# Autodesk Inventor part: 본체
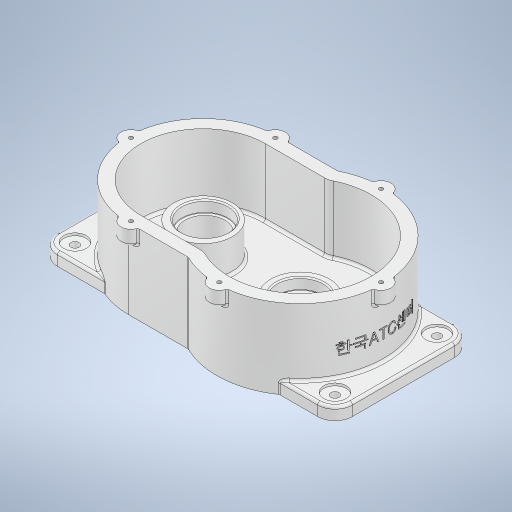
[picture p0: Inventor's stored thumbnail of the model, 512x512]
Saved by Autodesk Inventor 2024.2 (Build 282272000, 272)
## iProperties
Created: 2025-09
Part Number: 본체
Material: 알루미늄 6061
Document SubType Name: Modeling
Designer: home
Density: 2.7 g/cm^3
Appearance: 알루미늄 - 평지
Mass: 1651.06 g
Surface Area: 1337.51 cm^2
Volume: 611.503 cm^3
Author: home
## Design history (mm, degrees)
sketch "스케치1"
  geometry: L1 (118.5, -55)-(-118.5, -55); L2 (-118.5, -55)-(-118.5, 55); L3 (-118.5, 55)-(118.5, 55); L4 (118.5, 55)-(118.5, -55); 3 further points
  constraints: 8 end point, 2 midpoint, 2 parallel, 1 horizontal, 1 horizontal alignment, 1 perpendicular, 1 vertical alignment
  dimensions: "d0" = 110 distance of L3.end L1.start; "d1" = 237 distance of L1.start L1.end
extrude "돌출1" new body sketch "스케치1" distance "d2" = 10; taper "d3" = 0 deg
sketch "스케치2"
  geometry: L1 (-118.5, -55)-(118.5, -55) reference; L2 (-118.5, 55)-(-118.5, -55) reference; L3 (118.5, 55)-(-118.5, 55) reference; L4 (118.5, -55)-(118.5, 55) reference; L5 (42.5, -50)-(-4.988, -50); L6 (42.5, 50)-(-4.988, 50); L7 (-4.988, -60)-(42.5, -60); L8 (42.5, 60)-(-4.988, 60); A1 r 57 centre (-35.5, 0) between (-10.654, 51.3) and (-10.654, -51.3); A2 r 50 centre (42.5, 0) between (42.5, -50) and (42.5, 50); A3 r 13 centre (-4.988, -63) between (-4.988, -50) and (-10.654, -51.3); A4 r 13 centre (-4.988, 63) between (-10.654, 51.3) and (-4.988, 50); A5 r 3 centre (-4.988, -63) between (-4.988, -60) and (-6.295, -60.3); A6 r 60 centre (42.5, 0) between (42.5, -60) and (42.5, 60); A7 r 3 centre (-4.988, 63) between (-6.295, 60.3) and (-4.988, 60); A8 r 67 centre (-35.5, 0) between (-6.295, 60.3) and (-6.295, -60.3); 3 further points
  constraints: 18 point on circle, 8 centre point, 8 end point, 6 tangent, 2 horizontal, 2 horizontal alignment, 2 point on line, 1 equal radius, 5 other
  dimensions: "d4" = 114 diameter of A1; "d5" = 100 diameter of A2; "d6" = 78 distance of A1.centre A2.centre; "d11" = 76 distance from line of L4 A2.centre; "d12" = 13 radius of A3; "d13" = 10 radial gap between concentric circles of A1 A8
extrude "돌출3" join sketch "스케치2" distance "d14" = 64; taper "d15" = 0 deg
sketch "스케치3"
  geometry: 1 further point
sketch "스케치4"
  geometry: L1 (-66.479, 55)-(-118.5, 55) reference; L2 (-118.5, 55)-(-118.5, -55) reference; L3 (-118.5, -55)-(-66.479, -55) reference; A1 r 60 centre (-42.5, 0) between (-66.479, 55) and (-66.479, -55) reference; 1 further point
fillet "모깎기1" dims "d16" = 14
sketch "스케치5"
  geometry: L1 (20.533, -55)-(50.467, -55) reference; L2 (50.467, 55)-(20.533, 55) reference; A1 r 57 centre (35.5, 0) between (10.654, -51.3) and (10.654, 51.3) reference; 1 further point
extrude "돌출4" join sketch "스케치5" distance "d17" = 10; taper "d18" = 0 deg
sketch "스케치6"
  geometry: C1 r 9 at (-104.5, 41); C2 r 9 at (-104.5, -41); C3 r 9 at (104.5, 41); C4 r 9 at (104.5, -41); A1 r 14 centre (-104.5, 41) between (-104.5, 55) and (-118.5, 41) reference; A2 r 14 centre (-104.5, -41) between (-118.5, -41) and (-104.5, -55) reference; A3 r 14 centre (104.5, 41) between (118.5, 41) and (104.5, 55) reference; A4 r 14 centre (104.5, -41) between (104.5, -55) and (118.5, -41) reference; 1 further point
  constraints: 4 centre point, 4 coincident
  dimensions: "d19" = 18 diameter of C1; "d20" = 18 diameter of C3; "d21" = 18 diameter of C4; "d22" = 18 diameter of C2
extrude "돌출5" cut sketch "스케치6" distance "d23" = 2; taper "d24" = 0 deg
sketch "스케치7"
  geometry: C1 r 9 at (0, 0) reference; C2 r 9 at (209, 0) reference; C3 r 9 at (209, -82) reference; C4 r 9 at (0, -82) reference; C5 r 3.3 at (0, 0); C6 r 3.3 at (209, 0); C7 r 3.3 at (209, -82); C8 r 3.3 at (0, -82); 1 further point
  constraints: 4 centre point, 4 coincident
  dimensions: "d25" = 6.6 diameter of C5; "d26" = 6.6 diameter of C6; "d27" = 6.6 diameter of C7; "d28" = 6.6 diameter of C8
extrude "돌출6" cut sketch "스케치7" extent not by distance; stored distance "d29" = 2; taper "d30" = 0 deg
sketch "스케치8"
  geometry: L1 (-118.5, 41)-(-118.5, -41) reference; L2 (-118.5, 0)-(118.5, 0); L3 (118.5, -41)-(118.5, 41) reference; L4 (-42.5, 58)-(-42.5, -58); L5 (35.5, 65)-(35.5, -65); C1 r 8 at (-42.5, 58); C2 r 8 at (35.5, 65); C3 r 8 at (-100.5, 0); C4 r 8 at (100.5, 0); C5 r 8 at (-42.5, -58); C6 r 8 at (35.5, -65); A1 r 67 centre (35.5, 0) between (6.295, -60.3) and (6.295, 60.3) reference; A2 r 60 centre (-42.5, 0) between (-42.5, 60) and (-42.5, -60) reference; 4 further points
  constraints: 6 centre point, 6 end point, 5 equal radius, 5 midpoint, 2 horizontal alignment, 2 point on line, 2 vertical, 2 vertical alignment
  dimensions: "d31" = 16 diameter of C1; "d32" = 116 distance of L4.end L4.start; "d33" = 76 distance from line of L1 L4.start; "d35" = 58 distance of C3.centre A2.centre; "d36" = 65 distance of A1.centre C4.centre; "d37" = 78 horizontal distance of L5.start L4.start; "d38" = 130 distance of L5.end L5.start
extrude "돌출7" join sketch "스케치8" distance "d39" = 12; taper "d40" = 0 deg
sketch "스케치9"
  geometry: A1 r 8 centre (-42.5, 58) between (-34.754, 60) and (-50.361, 59.483) reference; A2 r 8 centre (35.5, 65) between (43.351, 66.538) and (27.649, 66.538) reference; A3 r 8 centre (100.5, 0) between (102.038, -7.851) and (102.038, 7.851) reference; A4 r 8 centre (35.5, -65) between (27.649, -66.538) and (43.351, -66.538) reference; A5 r 8 centre (-42.5, -58) between (-50.361, -59.483) and (-34.754, -60) reference; A6 r 8 centre (-100.5, 0) between (-101.983, 7.861) and (-101.983, -7.861) reference; 7 further points
  constraints: 6 coincident
hole "구멍1" sketch "스케치9" at (-42.5, 58), (35.5, 65), (100.5, 0), (35.5, -65), (-42.5, -58), (-100.5, 0) diameter "d41" = 3.242; stored, may be unused: countersink angle "d45" = 90 deg, drill point angle "d47" = 118 deg; dims "d42" = 8, "d43" = 4, "d44" = 2, "d46" = 10
sketch "스케치10"
  geometry: C1 r 23.5 at (-42.5, 0); A1 r 50 centre (-42.5, 0) between (-42.5, 50) and (-42.5, -50) reference; 1 further point
  constraints: 1 centre point, 1 coincident
  dimensions: "d48" = 47 diameter of C1
extrude "돌출8" join sketch "스케치10" distance "d49" = 26; taper "d50" = 0 deg
sketch "스케치11"
  geometry: C1 r 23.5 at (35.5, 0); A1 r 57 centre (35.5, 0) between (10.654, -51.3) and (10.654, 51.3) reference; 1 further point
  constraints: 1 centre point, 1 coincident
  dimensions: "d51" = 47 diameter of C1
extrude "돌출9" join sketch "스케치11" distance "d52" = 12; taper "d53" = 0 deg
sketch "스케치12"
  geometry: C1 r 18.5 at (0, 1.464); 1 further point
  constraints: 1 centre point
  dimensions: "d54" = 37 diameter of C1
extrude "돌출10" cut sketch "스케치12" distance "d55" = 9; taper "d56" = 0 deg
sketch "스케치13"
  geometry: C1 r 23.5 at (0, 0) reference; C2 r 18.5 at (0, 0); 1 further point
  constraints: 1 centre point, 1 coincident
  dimensions: "d57" = 37 diameter of C2
extrude "돌출11" cut sketch "스케치13" distance "d58" = 9; taper "d59" = 0 deg
sketch "스케치14"
  geometry: C1 r 18.5 at (0, 0) reference; C2 r 16 at (0, 0); 1 further point
  constraints: 1 centre point, 1 coincident
  dimensions: "d60" = 32 diameter of C2
extrude "돌출12" cut sketch "스케치14" distance "d61" = 16; taper "d62" = 0 deg
sketch "스케치15"
  geometry: C1 r 16 at (0, 0) reference; C2 r 14 at (0, 0); 1 further point
  constraints: 1 centre point, 1 coincident
  dimensions: "d63" = 28 diameter of C2
extrude "돌출13" cut sketch "스케치15" distance "d64" = 3; taper "d65" = 0 deg
fillet "모깎기2" dims "d66" = 0.3
chamfer "모따기1" distance "d67" = 1; stored, may be unused: second distance "d68" = 2, angle "d69" = 45 deg
sketch "스케치16"
  geometry: C1 r 23.5 at (35.5, 0) reference; C2 r 17.5 at (35.5, 0); 1 further point
  constraints: 1 centre point, 1 coincident
  dimensions: "d70" = 35 diameter of C2
extrude "돌출14" cut sketch "스케치16" distance "d71" = 8.3; taper "d72" = 0 deg
chamfer "모따기2" distance "d73" = 0.8; stored, may be unused: second distance "d74" = 2, angle "d75" = 30 deg
sketch "스케치17"
  geometry: C1 r 17.5 at (0, 0) reference; C2 r 15 at (0, 0); 1 further point
  constraints: 1 centre point, 1 coincident
  dimensions: "d76" = 30 diameter of C2
extrude "돌출15" cut sketch "스케치17" extent not by distance; stored distance "d77" = 0; taper "d78" = 0 deg
fillet "모깎기3" dims "d79" = 0.3
node "작업 평면1"
sketch "스케치18"
  geometry: L1 (0, -67)-(52, -67) reference; L2 (0, 41)-(0, -41) reference; L3 (64, -7.851)-(52, -7.851) reference; L4 (64, -7.851)-(64, 7.851) reference; 3 further points
  constraints: 1 horizontal alignment, 1 midpoint, 1 other
  dimensions: "d82" = 30 distance from line of L2 point (30, 0)
feature "엠보싱1" sketch "스케치18" dims "d83" = 0.5, "d84" = 0
chamfer "모따기3" distance "d85" = 1; stored, may be unused: second distance "d86" = 2, angle "d87" = 30 deg
fillet "모깎기4" dims "d88" = 2
fillet "모깎기5" dims "d89" = 2
fillet "모깎기6" dims "d90" = 2
fillet "모깎기7" dims "d91" = 0.3
fillet "모깎기8" dims "d92" = 0.3
node "솔리드1"
feature "A9D066F2-1C7D-4E18-AEED-F7BC21143FA4" dims "d41" = 3.242, "d42" = 8, "d43" = 4, "d44" = 2, "d45" = 90 deg, "d46" = 10, "d47" = 118 deg
